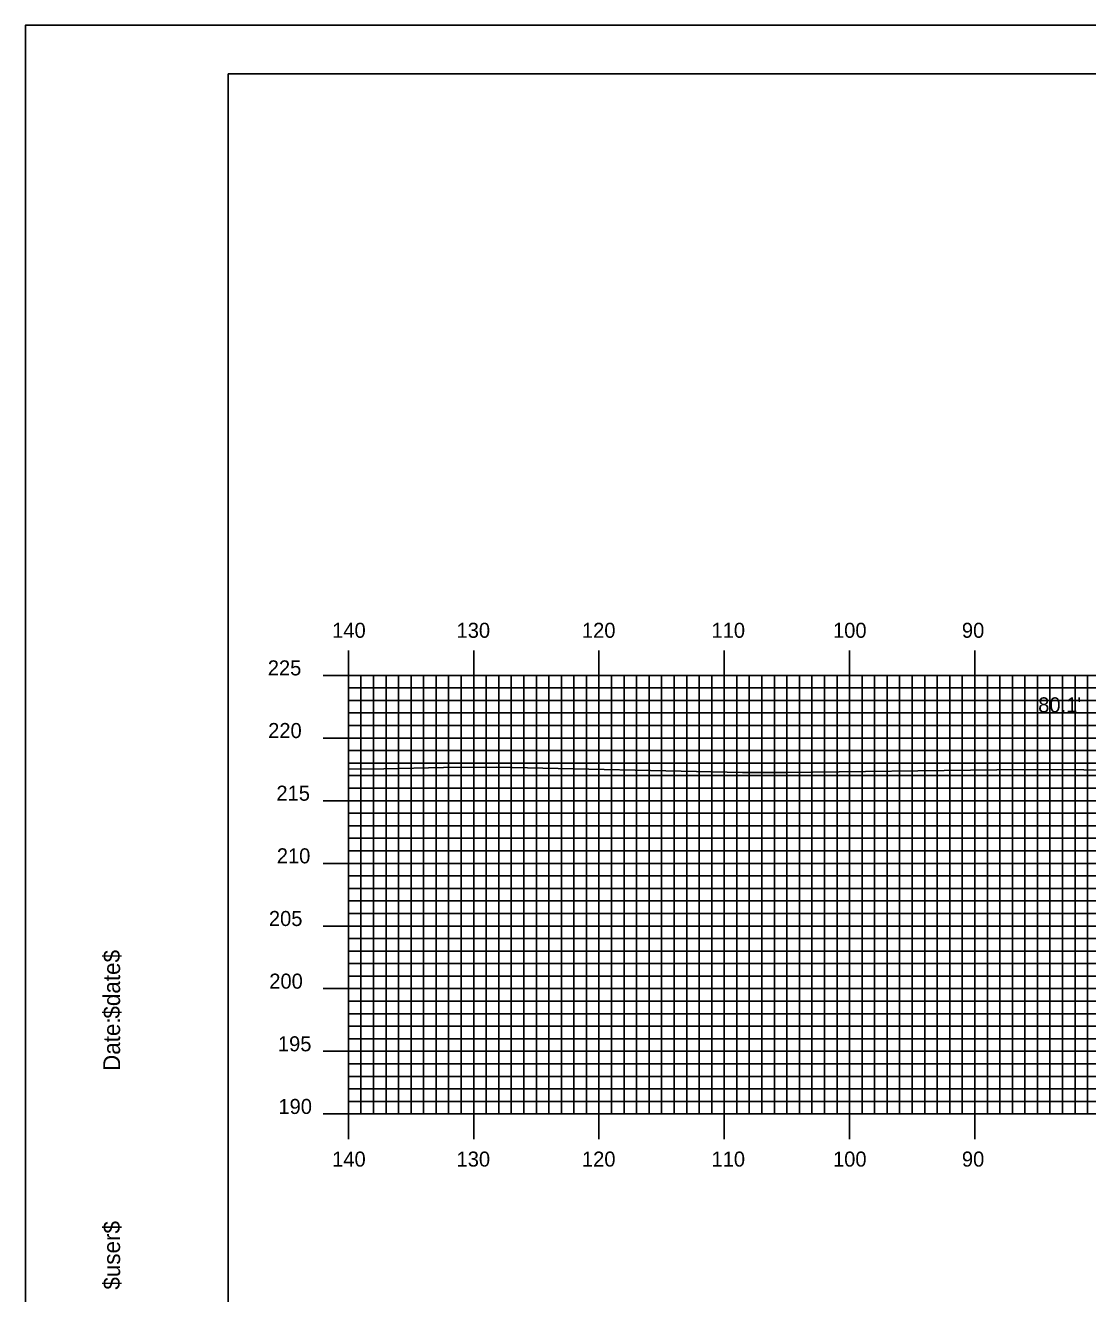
# Model space of a CAD drawing. Extents: x 1800355 to 1800699, y 442591 to 442811.
# Drawn here: x 1800355.2 to 1800440, y 442709.3 to 442810.5 of the extents above; entities that cross this region are included whole.
import ezdxf

# ---------------------------------------------------------------- set-up
doc = ezdxf.new("R2010")
doc.units = 0
for name, color, linetype in [('BORDER', 7, 'Continuous'), ('D_Text_Standard', 7, 'Continuous'), ('H_V ANNOTATION', 7, 'Continuous'), ('MAJOR', 7, 'Continuous'), ('MINOR', 7, 'Continuous'), ('PLOT BOUNDARY', 7, 'Continuous'), ('S_Roadway_Centerline', 7, 'Continuous')]:
    doc.layers.add(name, color=color, linetype=linetype)

msp = doc.modelspace()

# ---------------------------------------------------------------- linework, layer by layer
at = {"layer": 'BORDER'}
msp.add_lwpolyline([(1800371.44, 442596.67), (1800691.44, 442596.67), (1800691.44, 442806.67), (1800371.44, 442806.67)], close=True, dxfattribs=at)
at = {"layer": 'MAJOR'}
for p, q in [((1800381.04, 442760.67), (1800381.04, 442758.67)), ((1800391.04, 442760.67), (1800391.04, 442758.67)), ((1800401.04, 442760.67), (1800401.04, 442758.67)), ((1800411.04, 442760.67), (1800411.04, 442758.67)), ((1800421.04, 442760.67), (1800421.04, 442758.67)), ((1800431.04, 442760.67), (1800431.04, 442758.67)), ((1800379.03, 442758.67), (1800381.04, 442758.67)), ((1800381.04, 442758.67), (1800661.04, 442758.67)), ((1800381.04, 442723.67), (1800381.04, 442758.67)), ((1800381.04, 442723.67), (1800381.04, 442758.67)), ((1800381.04, 442758.67), (1800661.04, 442758.67)), ((1800391.04, 442723.67), (1800391.04, 442758.67)), ((1800401.04, 442723.67), (1800401.04, 442758.67)), ((1800411.04, 442723.67), (1800411.04, 442758.67)), ((1800421.04, 442723.67), (1800421.04, 442758.67)), ((1800431.04, 442723.67), (1800431.04, 442758.67)), ((1800379.03, 442753.67), (1800381.04, 442753.67)), ((1800381.04, 442753.67), (1800661.04, 442753.67)), ((1800379.03, 442748.67), (1800381.04, 442748.67)), ((1800381.04, 442748.67), (1800661.04, 442748.67)), ((1800379.03, 442743.67), (1800381.04, 442743.67)), ((1800381.04, 442743.67), (1800661.04, 442743.67)), ((1800379.03, 442738.67), (1800381.04, 442738.67)), ((1800381.04, 442738.67), (1800661.04, 442738.67)), ((1800379.03, 442733.67), (1800381.04, 442733.67)), ((1800381.04, 442733.67), (1800661.04, 442733.67)), ((1800379.03, 442728.67), (1800381.04, 442728.67)), ((1800381.04, 442728.67), (1800661.04, 442728.67)), ((1800379.03, 442723.67), (1800381.04, 442723.67)), ((1800381.04, 442723.67), (1800661.04, 442723.67)), ((1800381.04, 442723.67), (1800661.04, 442723.67)), ((1800381.04, 442721.66), (1800381.04, 442723.67)), ((1800391.04, 442721.66), (1800391.04, 442723.67)), ((1800401.04, 442721.66), (1800401.04, 442723.67)), ((1800411.04, 442721.66), (1800411.04, 442723.67)), ((1800421.04, 442721.66), (1800421.04, 442723.67)), ((1800431.04, 442721.66), (1800431.04, 442723.67))]:
    msp.add_line(p, q, dxfattribs=at)
at = {"layer": 'MINOR'}
for p, q in [((1800382.04, 442723.67), (1800382.04, 442758.67)), ((1800383.04, 442723.67), (1800383.04, 442758.67)), ((1800384.04, 442723.67), (1800384.04, 442758.67)), ((1800385.04, 442723.67), (1800385.04, 442758.67)), ((1800386.04, 442723.67), (1800386.04, 442758.67)), ((1800387.04, 442723.67), (1800387.04, 442758.67)), ((1800388.04, 442723.67), (1800388.04, 442758.67)), ((1800389.04, 442723.67), (1800389.04, 442758.67)), ((1800390.04, 442723.67), (1800390.04, 442758.67)), ((1800392.04, 442723.67), (1800392.04, 442758.67)), ((1800393.04, 442723.67), (1800393.04, 442758.67)), ((1800394.04, 442723.67), (1800394.04, 442758.67)), ((1800395.04, 442723.67), (1800395.04, 442758.67)), ((1800396.04, 442723.67), (1800396.04, 442758.67)), ((1800397.04, 442723.67), (1800397.04, 442758.67)), ((1800398.04, 442723.67), (1800398.04, 442758.67)), ((1800399.04, 442723.67), (1800399.04, 442758.67)), ((1800400.04, 442723.67), (1800400.04, 442758.67)), ((1800402.04, 442723.67), (1800402.04, 442758.67)), ((1800403.04, 442723.67), (1800403.04, 442758.67)), ((1800404.04, 442723.67), (1800404.04, 442758.67)), ((1800405.04, 442723.67), (1800405.04, 442758.67)), ((1800406.04, 442723.67), (1800406.04, 442758.67)), ((1800407.04, 442723.67), (1800407.04, 442758.67)), ((1800408.04, 442723.67), (1800408.04, 442758.67)), ((1800409.04, 442723.67), (1800409.04, 442758.67)), ((1800410.04, 442723.67), (1800410.04, 442758.67)), ((1800412.04, 442723.67), (1800412.04, 442758.67)), ((1800413.04, 442723.67), (1800413.04, 442758.67)), ((1800414.04, 442723.67), (1800414.04, 442758.67)), ((1800415.04, 442723.67), (1800415.04, 442758.67)), ((1800416.04, 442723.67), (1800416.04, 442758.67)), ((1800417.04, 442723.67), (1800417.04, 442758.67)), ((1800418.04, 442723.67), (1800418.04, 442758.67)), ((1800419.04, 442723.67), (1800419.04, 442758.67)), ((1800420.04, 442723.67), (1800420.04, 442758.67)), ((1800422.04, 442723.67), (1800422.04, 442758.67)), ((1800423.04, 442723.67), (1800423.04, 442758.67)), ((1800424.04, 442723.67), (1800424.04, 442758.67)), ((1800425.04, 442723.67), (1800425.04, 442758.67)), ((1800426.04, 442723.67), (1800426.04, 442758.67)), ((1800427.04, 442723.67), (1800427.04, 442758.67)), ((1800428.04, 442723.67), (1800428.04, 442758.67)), ((1800429.04, 442723.67), (1800429.04, 442758.67)), ((1800430.04, 442723.67), (1800430.04, 442758.67)), ((1800432.04, 442723.67), (1800432.04, 442758.67)), ((1800433.04, 442723.67), (1800433.04, 442758.67)), ((1800434.04, 442723.67), (1800434.04, 442758.67)), ((1800435.04, 442723.67), (1800435.04, 442758.67)), ((1800436.04, 442723.67), (1800436.04, 442758.67)), ((1800437.04, 442723.67), (1800437.04, 442758.67)), ((1800438.04, 442723.67), (1800438.04, 442758.67)), ((1800439.04, 442723.67), (1800439.04, 442758.67)), ((1800440.04, 442723.67), (1800440.04, 442758.67)), ((1800381.04, 442757.67), (1800661.04, 442757.67)), ((1800381.04, 442757.67), (1800383.04, 442757.67)), ((1800381.04, 442756.67), (1800661.04, 442756.67)), ((1800381.04, 442756.67), (1800383.04, 442756.67)), ((1800381.04, 442755.67), (1800661.04, 442755.67)), ((1800381.04, 442755.67), (1800383.04, 442755.67)), ((1800381.04, 442754.67), (1800661.04, 442754.67)), ((1800381.04, 442754.67), (1800383.04, 442754.67)), ((1800381.04, 442752.67), (1800661.04, 442752.67)), ((1800381.04, 442752.67), (1800383.04, 442752.67)), ((1800381.04, 442751.67), (1800661.04, 442751.67)), ((1800381.04, 442751.67), (1800383.04, 442751.67)), ((1800381.04, 442750.67), (1800661.04, 442750.67)), ((1800381.04, 442750.67), (1800383.04, 442750.67)), ((1800381.04, 442749.67), (1800661.04, 442749.67)), ((1800381.04, 442749.67), (1800383.04, 442749.67)), ((1800381.04, 442747.67), (1800661.04, 442747.67)), ((1800381.04, 442747.67), (1800383.04, 442747.67)), ((1800381.04, 442746.67), (1800661.04, 442746.67)), ((1800381.04, 442746.67), (1800383.04, 442746.67)), ((1800381.04, 442745.67), (1800661.04, 442745.67)), ((1800381.04, 442745.67), (1800383.04, 442745.67)), ((1800381.04, 442744.67), (1800661.04, 442744.67)), ((1800381.04, 442744.67), (1800383.04, 442744.67)), ((1800381.04, 442742.67), (1800661.04, 442742.67)), ((1800381.04, 442742.67), (1800383.04, 442742.67)), ((1800381.04, 442741.67), (1800661.04, 442741.67)), ((1800381.04, 442741.67), (1800383.04, 442741.67)), ((1800381.04, 442740.67), (1800661.04, 442740.67)), ((1800381.04, 442740.67), (1800383.04, 442740.67)), ((1800381.04, 442739.67), (1800661.04, 442739.67)), ((1800381.04, 442739.67), (1800383.04, 442739.67)), ((1800381.04, 442737.67), (1800661.04, 442737.67)), ((1800381.04, 442737.67), (1800383.04, 442737.67)), ((1800381.04, 442736.67), (1800661.04, 442736.67)), ((1800381.04, 442736.67), (1800383.04, 442736.67)), ((1800381.04, 442735.67), (1800661.04, 442735.67)), ((1800381.04, 442735.67), (1800383.04, 442735.67)), ((1800381.04, 442734.67), (1800661.04, 442734.67)), ((1800381.04, 442734.67), (1800383.04, 442734.67)), ((1800381.04, 442732.67), (1800661.04, 442732.67)), ((1800381.04, 442732.67), (1800383.04, 442732.67)), ((1800381.04, 442731.67), (1800661.04, 442731.67)), ((1800381.04, 442731.67), (1800383.04, 442731.67)), ((1800381.04, 442730.67), (1800661.04, 442730.67)), ((1800381.04, 442730.67), (1800383.04, 442730.67)), ((1800381.04, 442729.67), (1800661.04, 442729.67)), ((1800381.04, 442729.67), (1800383.04, 442729.67)), ((1800381.04, 442727.67), (1800661.04, 442727.67)), ((1800381.04, 442727.67), (1800383.04, 442727.67)), ((1800381.04, 442726.67), (1800661.04, 442726.67)), ((1800381.04, 442726.67), (1800383.04, 442726.67)), ((1800381.04, 442725.67), (1800661.04, 442725.67)), ((1800381.04, 442725.67), (1800383.04, 442725.67)), ((1800381.04, 442724.67), (1800661.04, 442724.67)), ((1800381.04, 442724.67), (1800383.04, 442724.67))]:
    msp.add_line(p, q, dxfattribs=at)
at = {"layer": 'PLOT BOUNDARY'}
msp.add_lwpolyline([(1800355.25, 442590.55), (1800695.25, 442590.55), (1800695.25, 442810.55), (1800355.25, 442810.55)], close=True, dxfattribs=at)
at = {"layer": 'S_Roadway_Centerline'}
msp.add_lwpolyline([(1800381.04, 442751.18), (1800383.86, 442751.21), (1800388.64, 442751.31), (1800392.89, 442751.36), (1800412.49, 442750.92), (1800416.01, 442750.91), (1800432.79, 442751.13), (1800438.09, 442751.16), (1800457.88, 442750.84)], dxfattribs=at)

# ---------------------------------------------------------------- texts
at = {"layer": 'BORDER'}
for s, p in [('$date$', (1800362.81, 442731.28)), ('Date:', (1800362.81, 442727.1)), ('$user$', (1800362.81, 442709.65))]:
    msp.add_text(s, height=1.339, rotation=90, dxfattribs=at).set_placement(p)
at = {"layer": 'D_Text_Standard'}
msp.add_text("80.1'", height=1.2, dxfattribs=at).set_placement((1800436.1, 442755.72))
at = {"layer": 'H_V ANNOTATION'}
for s, p in [('140', (1800379.74, 442761.67)), ('130', (1800389.67, 442761.67)), ('120', (1800399.68, 442761.67)), ('110', (1800410.02, 442761.67)), ('100', (1800419.72, 442761.67)), ('90', (1800430.01, 442761.67)), ('225', (1800374.6, 442758.67)), ('220', (1800374.63, 442753.67)), ('215', (1800375.29, 442748.67)), ('210', (1800375.32, 442743.67)), ('205', (1800374.69, 442738.67)), ('200', (1800374.72, 442733.67)), ('195', (1800375.41, 442728.67)), ('190', (1800375.45, 442723.67)), ('140', (1800379.74, 442719.47)), ('130', (1800389.67, 442719.47)), ('120', (1800399.68, 442719.47)), ('110', (1800410.02, 442719.47)), ('100', (1800419.72, 442719.47)), ('90', (1800430.01, 442719.47))]:
    msp.add_text(s, height=1.2, dxfattribs=at).set_placement(p)
at = {"layer": 'MAJOR'}
msp.add_text('-', height=0.012, dxfattribs=at).set_placement((1800381.03, 442723.67))

doc.saveas('drawing.dxf')
